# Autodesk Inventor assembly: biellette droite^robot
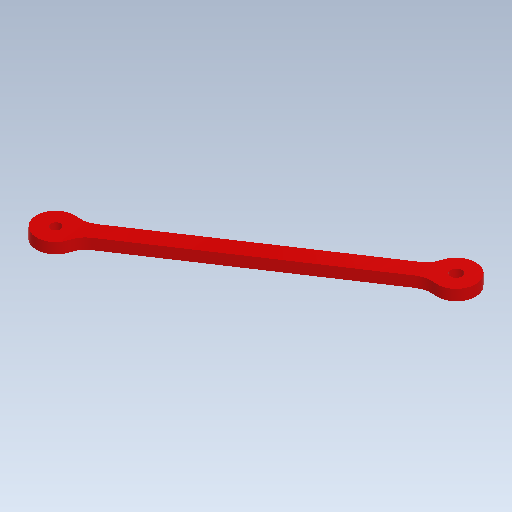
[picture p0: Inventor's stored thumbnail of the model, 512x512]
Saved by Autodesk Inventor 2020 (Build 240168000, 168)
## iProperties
Created: 2018-10
Part Number: biellette droite^robot
Document SubType Name: Assembly
Designer: bruno
Sending System: SolidWorks 2016
Last Author: Prof
Last Saved: 2018-10-03
Author: bruno
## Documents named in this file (2)
- C:\Users\bruno\Documents\Systèmes\Mallette Bras robotisé (273265)\Dossier ressources\Maquette Dobot SW2016\biellette droite^robot.iam
- C:\Users\bruno\Documents\Systèmes\Mallette Bras robotisé (273265)\Dossier ressources\Maquette Dobot SW2016\BREP_2-964.ipt
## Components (1 placed, 1 different names)
1. BREP_2-964:1
